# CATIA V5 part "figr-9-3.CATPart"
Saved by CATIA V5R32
Part number: Part1
Bounding box of the stored display mesh (mm): x -25 to 69.61, y -164.735 to 0, z 0 to 45
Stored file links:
  D:\PROJECTS\Project 2022\CATIA V5 6R 2022\Resources\Part Files\c09_catia_v5_6r2022_prt\c09_catia_v5_6r2022_prt\figr-9-3.CATPart
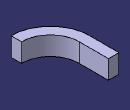
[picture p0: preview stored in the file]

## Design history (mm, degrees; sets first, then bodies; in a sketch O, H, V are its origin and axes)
Body1 (main body)
  Sketch1 on xy-plane, origin (0, 0, 0), H (1, 0, 0), V (0, 1, 0)
    line L1 (0, 0) -> (0, -70.1255)
    arc A1 centre (69.6095, -70.1255) radius 69.6095 from (0, -70.1255) to (69.6095, -139.7351) ccw
    vertical: L1 V
    tangency: A1 L1
  Sketch2 on zx-plane, origin (0, 0, 0), H (-1, 0, 0), V (0, 0, 1)
    point P1 (0, 0)
    line L1 (0, 0) -> (25, 0)
    line L2 (25, 0) -> (25, 45)
    line L3 (25, 45) -> (0, 45)
    line L4 (0, 45) -> (0, 0)
    length L3 = 25
    length L2 = 45
    coincidence: P1 H, P1 O
    horizontal: L1 H, L3 H
    vertical: L2 V, L4 V
  Rib1: profile Sketch2, centre curve Sketch1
